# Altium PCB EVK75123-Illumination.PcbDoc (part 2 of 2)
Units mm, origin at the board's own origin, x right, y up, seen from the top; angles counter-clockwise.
Board outline 80 x 50 mm, 4 copper layers (Top Layer, GND, VCC, Bottom Layer), stack 0.976 mm thick; 91 components, 44 nets, 247 pads, 1773 vias.
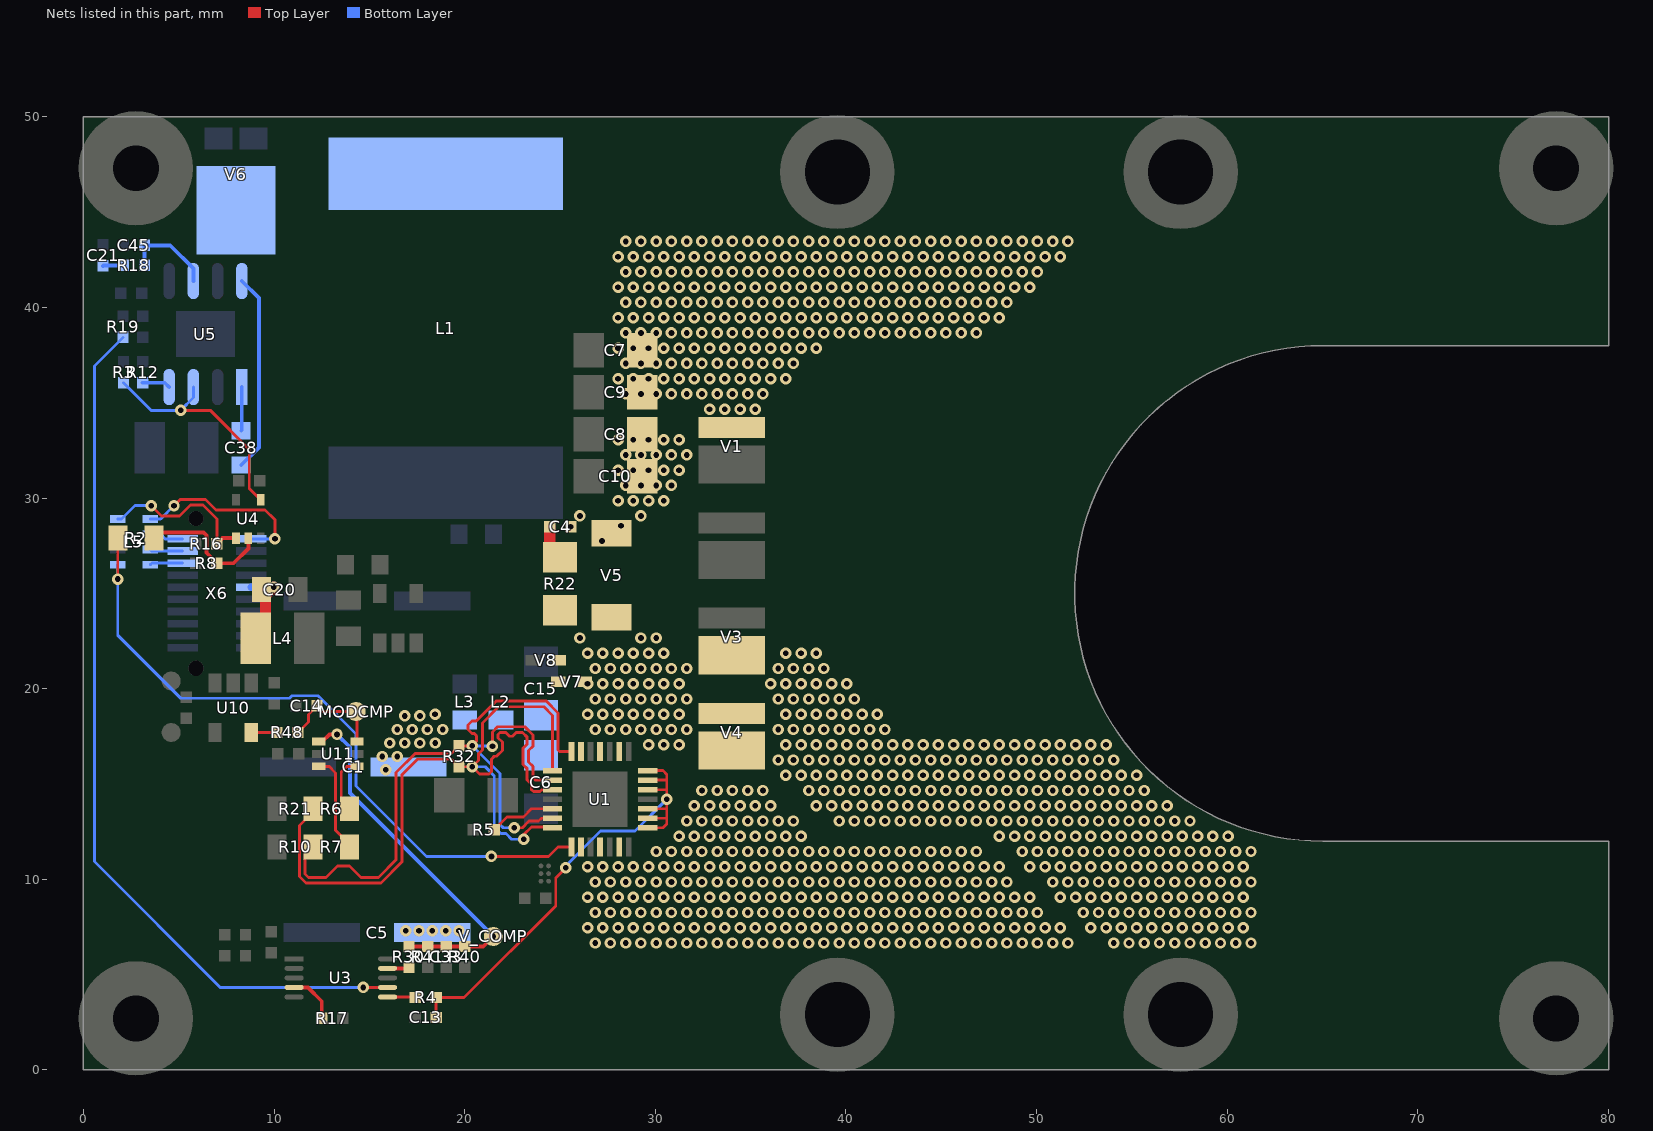
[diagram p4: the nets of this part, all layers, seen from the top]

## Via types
v1: diameter 0.6, hole 0.3, Top Layer to Bottom Layer, tented both sides, 1773 vias

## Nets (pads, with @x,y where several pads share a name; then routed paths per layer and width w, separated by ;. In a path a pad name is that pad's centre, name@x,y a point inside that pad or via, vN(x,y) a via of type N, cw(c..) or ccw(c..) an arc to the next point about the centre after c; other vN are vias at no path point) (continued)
LD3: V3.2 V4.1
  other v1: 54.044,6.659 54.844,6.659 55.644,6.659 56.444,6.659 57.244,6.659 58.044,6.659 58.844,6.659 59.644,6.659 60.444,6.659 61.244,6.659 52.844,7.459 53.644,7.459 54.444,7.459 55.244,7.459 56.044,7.459 56.844,7.459 57.644,7.459 58.444,7.459 59.244,7.459 60.044,7.459 60.844,7.459 52.444,8.259 53.244,8.259 54.044,8.259 54.844,8.259 55.644,8.259 56.444,8.259 57.244,8.259 58.044,8.259 58.844,8.259 59.644,8.259 60.444,8.259 61.244,8.259 51.244,9.059 52.044,9.059 52.844,9.059 53.644,9.059 54.444,9.059 55.244,9.059 56.044,9.059 56.844,9.059 57.644,9.059 58.444,9.059 59.244,9.059 60.044,9.059 60.844,9.059 50.844,9.859 51.644,9.859 52.444,9.859 53.244,9.859 54.044,9.859 54.844,9.859 55.644,9.859 56.444,9.859 57.244,9.859 58.044,9.859 58.844,9.859 59.644,9.859 60.444,9.859 61.244,9.859 49.644,10.659 50.444,10.659 51.244,10.659 52.044,10.659 52.844,10.659 53.644,10.659 54.444,10.659 55.244,10.659 56.044,10.659 56.844,10.659 57.644,10.659 58.444,10.659 59.244,10.659 60.044,10.659 60.844,10.659 49.244,11.459 50.044,11.459 50.844,11.459 51.644,11.459 52.444,11.459 53.244,11.459 54.044,11.459 54.844,11.459 55.644,11.459 56.444,11.459 57.244,11.459 58.044,11.459 58.844,11.459 59.644,11.459 60.444,11.459 61.244,11.459 48.044,12.259 48.844,12.259 49.644,12.259 50.444,12.259 51.244,12.259 52.044,12.259 52.844,12.259 53.644,12.259 54.444,12.259 55.244,12.259 56.044,12.259 56.844,12.259 57.644,12.259 58.444,12.259 59.244,12.259 60.044,12.259 39.644,13.059 40.444,13.059 41.244,13.059 42.044,13.059 42.844,13.059 43.644,13.059 44.444,13.059 45.244,13.059 46.044,13.059 46.844,13.059 47.644,13.059 48.444,13.059 49.244,13.059 50.044,13.059 50.844,13.059 51.644,13.059 52.444,13.059 53.244,13.059 54.044,13.059 54.844,13.059 55.644,13.059 56.444,13.059 57.244,13.059 58.044,13.059 38.444,13.859 39.244,13.859 40.044,13.859 40.844,13.859 41.644,13.859 42.444,13.859 43.244,13.859 44.044,13.859 44.844,13.859 45.644,13.859 46.444,13.859 47.244,13.859 48.044,13.859 48.844,13.859 49.644,13.859 50.444,13.859 51.244,13.859 52.044,13.859 52.844,13.859 53.644,13.859 54.444,13.859 55.244,13.859 56.044,13.859 56.844,13.859 38.044,14.659 38.844,14.659 39.644,14.659 40.444,14.659 41.244,14.659 42.044,14.659 42.844,14.659 43.644,14.659 44.444,14.659 45.244,14.659 46.044,14.659 46.844,14.659 47.644,14.659 48.444,14.659 49.244,14.659 50.044,14.659 50.844,14.659 51.644,14.659 52.444,14.659 53.244,14.659 54.044,14.659 54.844,14.659 55.644,14.659 36.844,15.459 37.644,15.459 38.444,15.459 39.244,15.459 40.044,15.459 40.844,15.459 41.644,15.459 42.444,15.459 43.244,15.459 44.044,15.459 44.844,15.459 45.644,15.459 46.444,15.459 47.244,15.459 48.044,15.459 48.844,15.459 49.644,15.459 50.444,15.459 51.244,15.459 52.044,15.459 52.844,15.459 53.644,15.459 54.444,15.459 55.244,15.459 36.444,16.259 37.244,16.259 38.044,16.259 38.844,16.259 39.644,16.259 40.444,16.259 41.244,16.259 42.044,16.259 42.844,16.259 43.644,16.259 44.444,16.259 45.244,16.259 46.044,16.259 46.844,16.259 47.644,16.259 48.444,16.259 49.244,16.259 50.044,16.259 50.844,16.259 51.644,16.259 52.444,16.259 53.244,16.259 54.044,16.259 36.844,17.059 37.644,17.059 38.444,17.059 39.244,17.059 40.044,17.059 40.844,17.059 41.644,17.059 42.444,17.059 43.244,17.059 44.044,17.059 44.844,17.059 45.644,17.059 46.444,17.059 47.244,17.059 48.044,17.059 48.844,17.059 49.644,17.059 50.444,17.059 51.244,17.059 52.044,17.059 52.844,17.059 53.644,17.059 36.444,17.859 37.244,17.859 38.044,17.859 38.844,17.859 39.644,17.859 40.444,17.859 41.244,17.859 42.044,17.859 36.844,18.659 37.644,18.659 38.444,18.659 39.244,18.659 40.044,18.659 40.844,18.659 41.644,18.659 36.444,19.459 37.244,19.459 38.044,19.459 38.844,19.459 39.644,19.459 40.444,19.459 36.044,20.259 36.844,20.259 37.644,20.259 38.444,20.259 39.244,20.259 40.044,20.259 36.444,21.059 37.244,21.059 38.044,21.059 38.844,21.059 36.844,21.859 37.644,21.859 38.444,21.859
LDEN: L5.4 R16.1 U4.1 | length 8.7
  Top Layer w0.15: v1(3.55,29.6) 4.096,29.054 5.032,29.054 5.608,29.63 6.27,29.63 7,28.9 R16.1@7,27.6
  Top Layer w0.2: R16.1@7,27.6 7.3,27.9 U4.1@8,27.9
  Bottom Layer w0.15: L5.4@1.8,28.9 2,28.9 2.7,29.6 v1(3.55,29.6)
LDK: R22.1 U1.9 U1.11 U1.13 U1.23 U1.25 U1.27 V4.2 V5.1 V7.2
  other v1: 26.844,6.659 27.644,6.659 28.444,6.659 29.244,6.659 30.044,6.659 30.844,6.659 31.644,6.659 32.444,6.659 33.244,6.659 34.044,6.659 34.844,6.659 35.644,6.659 36.444,6.659 37.244,6.659 38.044,6.659 38.844,6.659 39.644,6.659 40.444,6.659 41.244,6.659 42.044,6.659 42.844,6.659 43.644,6.659 44.444,6.659 45.244,6.659 46.044,6.659 46.844,6.659 47.644,6.659 48.444,6.659 49.244,6.659 50.044,6.659 50.844,6.659 51.644,6.659 26.444,7.459 27.244,7.459 28.044,7.459 28.844,7.459 29.644,7.459 30.444,7.459 31.244,7.459 32.044,7.459 32.844,7.459 33.644,7.459 34.444,7.459 35.244,7.459 36.044,7.459 36.844,7.459 37.644,7.459 38.444,7.459 39.244,7.459 40.044,7.459 40.844,7.459 41.644,7.459 42.444,7.459 43.244,7.459 44.044,7.459 44.844,7.459 45.644,7.459 46.444,7.459 47.244,7.459 48.044,7.459 48.844,7.459 49.644,7.459 50.444,7.459 51.244,7.459 26.844,8.259 27.644,8.259 28.444,8.259 29.244,8.259 30.044,8.259 30.844,8.259 31.644,8.259 32.444,8.259 33.244,8.259 34.044,8.259 34.844,8.259 35.644,8.259 36.444,8.259 37.244,8.259 38.044,8.259 38.844,8.259 39.644,8.259 40.444,8.259 41.244,8.259 42.044,8.259 42.844,8.259 43.644,8.259 44.444,8.259 45.244,8.259 46.044,8.259 46.844,8.259 47.644,8.259 48.444,8.259 49.244,8.259 50.044,8.259 26.444,9.059 27.244,9.059 28.044,9.059 28.844,9.059 29.644,9.059 30.444,9.059 31.244,9.059 32.044,9.059 32.844,9.059 33.644,9.059 34.444,9.059 35.244,9.059 36.044,9.059 36.844,9.059 37.644,9.059 38.444,9.059 39.244,9.059 40.044,9.059 40.844,9.059 41.644,9.059 42.444,9.059 43.244,9.059 44.044,9.059 44.844,9.059 45.644,9.059 46.444,9.059 47.244,9.059 48.044,9.059 48.844,9.059 49.644,9.059 26.844,9.859 27.644,9.859 28.444,9.859 29.244,9.859 30.044,9.859 30.844,9.859 31.644,9.859 32.444,9.859 33.244,9.859 34.044,9.859 34.844,9.859 35.644,9.859 36.444,9.859 37.244,9.859 38.044,9.859 38.844,9.859 39.644,9.859 40.444,9.859 41.244,9.859 42.044,9.859 42.844,9.859 43.644,9.859 44.444,9.859 45.244,9.859 46.044,9.859 46.844,9.859 47.644,9.859 48.444,9.859 26.444,10.659 27.244,10.659 28.044,10.659 28.844,10.659 29.644,10.659 30.444,10.659 31.244,10.659 32.044,10.659 32.844,10.659 33.644,10.659 34.444,10.659 35.244,10.659 36.044,10.659 36.844,10.659 37.644,10.659 38.444,10.659 39.244,10.659 40.044,10.659 40.844,10.659 41.644,10.659 42.444,10.659 43.244,10.659 44.044,10.659 44.844,10.659 45.644,10.659 46.444,10.659 47.244,10.659 48.044,10.659 30.044,11.459 30.844,11.459 31.644,11.459 32.444,11.459 33.244,11.459 34.044,11.459 34.844,11.459 35.644,11.459 36.444,11.459 37.244,11.459 38.044,11.459 38.844,11.459 39.644,11.459 40.444,11.459 41.244,11.459 42.044,11.459 42.844,11.459 43.644,11.459 44.444,11.459 45.244,11.459 46.044,11.459 46.844,11.459 31.244,12.259 32.044,12.259 32.844,12.259 33.644,12.259 34.444,12.259 35.244,12.259 36.044,12.259 36.844,12.259 37.644,12.259 31.644,13.059 32.444,13.059 33.244,13.059 34.044,13.059 34.844,13.059 35.644,13.059 36.444,13.059 37.244,13.059 32.044,13.859 32.844,13.859 33.644,13.859 34.444,13.859 35.244,13.859 36.044,13.859 32.444,14.659 33.244,14.659 34.044,14.659 34.844,14.659 35.644,14.659 29.644,17.059 30.444,17.059 31.244,17.059 26.844,17.859 27.644,17.859 28.444,17.859 29.244,17.859 30.044,17.859 30.844,17.859 31.644,17.859 26.444,18.659 27.244,18.659 28.044,18.659 28.844,18.659 29.644,18.659 30.444,18.659 31.244,18.659 26.844,19.459 27.644,19.459 28.444,19.459 29.244,19.459 30.044,19.459 30.844,19.459 31.644,19.459 26.444,20.259 27.244,20.259 28.044,20.259 28.844,20.259 29.644,20.259 30.444,20.259 31.244,20.259 26.844,21.059 27.644,21.059 28.444,21.059 29.244,21.059 30.044,21.059 30.844,21.059 31.644,21.059 26.444,21.859 27.244,21.859 28.044,21.859 28.844,21.859 29.644,21.859 30.444,21.859 26.044,22.659 29.244,22.659 30.044,22.659
MOD1_N: R7.2 U11.6 | length 5.2
  Top Layer w0.15: U11.6@12.35,15.925 12.875,15.925 13.225,15.575 13.225,12.575 13.95,11.85 R7.2@13.95,11.7
MOD1_P: R6.2 U11.1 | length 3.1
  Top Layer w0.15: R6.2@13.95,13.7 13.525,14.125 13.525,15.625 13.825,15.925 U11.1@14.35,15.925
MOD_CMP: C14.2 MODCMP.1 R48.2 U11.3 | length 5.6
  Top Layer w0.15: R48.2@11.25,17.7 11.8,18.25 11.8,18.65 C14.2@12.25,19.1 12.55,18.8 MODCMP.1@14.3,18.8 14.35,18.75 U11.3@14.35,17.225
MOD_N: R7.1 R10.1 R32.1 U1.14 U1.16 U1.20 | length 41.6
  Top Layer w0.15: R7.1@12.05,11.7 11.625,11.275 11.625,10.275 11.8,10.1 12.719,10.1 13.319,10.7 13.957,10.7 14.557,10.1 15.476,10.1 16.4,11.024 16.4,15.6 17.4,16.6 19.3,16.6 R32.1@19.7,17 v1(20.4,17) 20.625,17.225 20.625,17.525 20.5,17.65 20.375,17.65 20.175,17.85 20.175,18.1 20.375,18.3 20.6,18.3 21.65,19.35 24.274,19.35 24.9,18.724 24.9,16.775 24.975,16.7 U1.14@25.6,16.7 ; v1(21.452,16.977) 21.452,17.727 21.726,18 23.15,18 23.575,17.575 23.575,16.975 23.35,16.75 23.35,16.15 23.575,15.925 23.575,15.325 23.7,15.2 U1.16@24.6,15.2 ; v1(22.6,12.7) 23.026,12.7 23.376,13.05 23.875,13.05 24.025,13.2 U1.20@24.6,13.2
  Bottom Layer w0.15: v1(21.452,16.977) 21.429,17 v1(20.4,17) 21.85,15.55 21.85,12.874 22.024,12.7 v1(22.6,12.7)
MOD_P: R6.1 R21.1 R32.2 U1.15 U1.17 U1.21 | length 45.6
  Top Layer w0.15: R6.1@12.05,13.7 12.05,13.55 11.325,12.825 11.325,10.151 11.676,9.8 15.6,9.8 16.7,10.9 16.7,15.476 17.524,16.3 19.3,16.3 R32.2@19.7,15.9 v1(20.4,15.9) ; v1(23.1,12.1) 23.1,12.35 23.5,12.75 24.55,12.75 U1.21@24.6,12.7 ; U1.17@24.6,14.7 24.175,14.7 24.05,14.7 23.95,14.6 23.6,14.6 23.5,14.7 23.5,14.976 23.275,15.201 23.275,15.801 23.05,16.026 23.05,16.874 23.275,17.099 23.275,17.451 23.026,17.7 22.7,17.7 22.5,17.5 22.35,17.5 22.15,17.7 21.85,17.7 21.752,17.602 21.752,17.419 21.977,17.194 21.977,16.759 21.67,16.452 21.552,16.452 21.4,16.3 21.4,15.65 21.275,15.525 20.775,15.525 v1(20.4,15.9) ; U1.15@24.6,15.7 24.6,18.6 24.15,19.05 21.774,19.05 20.925,18.201 20.925,16.783 20.725,16.583 20.725,16.225 v1(20.4,15.9)
  Bottom Layer w0.15: v1(20.4,15.9) 21.076,15.9 21.55,15.426 21.55,12.75 21.9,12.4 22.157,12.4 22.457,12.1 v1(23.1,12.1)
MOD_SE: R48.1 U10.5 | length 1.3
  Top Layer w0.15: U10.5@8.8,17.7 R48.1@10.15,17.7
NERR: L5.1 R2.1 U1.22 | length 36.4
  Top Layer w0.15: v1(1.8,25.75) R2.1@1.8,27.9 ; v1(21.4,11.2) 24.4,11.2 24.9,11.7 U1.22@25.6,11.7
  Bottom Layer w0.15: L5.1@1.8,26.5 v1(1.8,25.75) 1.8,22.8 5.1,19.5 10.808,19.5 10.933,19.625 12.304,19.625 14.3,17.629 14.3,14.9 18,11.2 v1(21.4,11.2)
NERRR: R2.2 R8.1 U4.2 | length 7.2
  Top Layer w0.2: R2.2@3.7,27.9 3.995,28.195 6.305,28.195 6.45,28.05 6.45,27.125 R8.1@7,26.575 7.875,26.575 8.65,27.35 U4.2@8.65,27.9
NetC4_1: C4.1 R22.2 | length 1.1
  Top Layer w0.6: R22.2@24.45,27.45 C4.1@24.45,28.5
NetC13_2: C13.2 R4.1 U1.1 U1.2 U1.3 U1.5 U1.6 U1.7 | length 27.1
  Top Layer w0.15: C13.2@18.5,2.75 R4.1@18.5,3.8 19.968,3.8 24.775,8.607 24.775,10.075 v1(25.3,10.6) ; U1.1@29.6,12.7 30.4,12.7 30.6,12.9 30.6,13.2 ; U1.2@29.6,13.2 30.6,13.2 ; U1.3@29.6,13.7 30.6,13.7 ; U1.5@29.6,14.7 30.6,14.7 ; U1.6@29.6,15.2 30.6,15.2 ; U1.7@29.6,15.7 30.4,15.7 30.6,15.5 30.6,15.2 ; 30.6,13.2 30.6,13.7 ; 30.6,13.7 v1(30.6,14.2) 30.6,14.7 ; 30.6,14.7 30.6,15.2
  Bottom Layer w0.15: v1(25.3,10.6) 25.3,10.7 27.125,12.525 28.925,12.525 v1(30.6,14.2)
NetC20_2: C20.2 L4.1 X6.11 | length 4.2
  Top Layer w0.6: L4.1@9.05,22.65 9.05,23.25 9.55,23.75 9.55,24.885 v1(9.982,25.318)
  Bottom Layer w0.4: X6.11@8.8,25.318 v1(9.982,25.318)
NetC21_2: C21.2 R18.2 | length 1.1
  Bottom Layer w0.2: C21.2@1.025,42.175 1.05,42.2 R18.2@2.1,42.2
NetC38_2: C38.2 U5.1 | length 2.3
  Bottom Layer w0.2: C38.2@8.275,33.525 8.305,33.555 U5.1@8.305,35.82
NetC45_2: C45.2 R18.1 U5.6 | length 4.8
  Bottom Layer w0.2: R18.1@3.2,42.2 C45.2@3.2,43.25 4.55,43.25 5.765,42.035 U5.6@5.765,41.38
NetL5_5: L5.5 X6.19 | length 9.7
  Top Layer w0.15: v1(4.75,29.6) 5.08,29.93 6.394,29.93 6.949,29.375 9.525,29.375 10.042,28.858 v1(10.042,27.858)
  Bottom Layer w0.15: L5.5@3.5,28.9 4.05,28.9 v1(4.75,29.6) ; X6.19@8.8,27.858 v1(10.042,27.858)
NetL5_6: L5.6 X6.20 | length 1.8
  Bottom Layer w0.15: L5.6@3.5,28.1 4.05,28.1 4.292,27.858 X6.20@5.2,27.858
NetL5_7: L5.7 X6.18 | length 1.7
  Bottom Layer w0.15: L5.7@3.5,27.3 3.578,27.223 X6.18@5.2,27.223
NetL5_8: L5.8 X6.16 | length 1.7
  Bottom Layer w0.15: L5.8@3.5,26.5 3.588,26.588 X6.16@5.2,26.588
NetR5_1: R5.1 U1.19 | length 3.5
  Top Layer w0.15: R5.1@21.55,12.6 22.225,13.275 23.075,13.275 23.5,13.7 U1.19@24.6,13.7
NetR17_2: R17.2 U3.4 | length 2.7
  Top Layer w0.2: U3.4@11.05,4.325 11.775,4.325 12.5,3.6 R17.2@12.5,2.7
NetV7_1: V7.1 V8.2
PEN: R3.2 U4.4 U5.3 | length 12.4
  Top Layer w0.15: v1(5.1,34.6) 6.65,34.6 8.7,32.55 8.7,30.5 U4.4@9.3,29.9
  Bottom Layer w0.15: R3.2@2.1,36.05 3.55,34.6 v1(5.1,34.6) 5.765,35.265 U5.3@5.765,35.82
RT17V: R12.1 U5.4 | length 1.5
  Bottom Layer w0.2: R12.1@3.1,36.05 4.265,36.05 U5.4@4.495,35.82
SW17V: C38.1 L1.1 U5.8 V6.2 | length 10.4
  Bottom Layer w0.2: C38.1@8.275,31.725 9.2,32.65 9.2,40.485 U5.8@8.305,41.38
V_CI: R4.2 U3.6 | length 1.5
  Top Layer w0.15: U3.6@15.95,3.825 17.375,3.825 R4.2@17.4,3.8
V_CMP: C33.1 R30.2 R40.2 R41.1 U11.4 V_COMP.1 | length 19.7
  Top Layer w0.2: U11.4@12.35,17.225 12.525,17.225 12.9,17.6 v1(13.3,17.6) ; R30.2@17.075,6.475 20.975,6.475 v1(21.5,7)
  Bottom Layer w0.2: v1(13.3,17.6) 13.975,16.925 13.975,14.525 v1(21.5,7)
V_DAC_D: R30.1 U3.9 | length 1.1
  Top Layer w0.2: U3.9@15.95,5.325 17.025,5.325 R30.1@17.075,5.375
VLD: C1.1 C4.2 C5.1 C6.1 C7.2 C8.2 C9.2 C10.2 C15.2 L2.2 L3.2 V1.1 V5.2
  other v1: 16.9,7.3 17.6,7.3 18.3,7.3 19,7.3 19.7,7.3 15.856,15.741 15.669,16.441 16.456,16.441 16.063,17.15 16.85,17.15 17.65,17.15 18.45,17.15 16.456,17.859 17.244,17.859 18.044,17.859 18.844,17.859 16.85,18.567 17.65,18.567 18.444,18.659 27.2,27.75 25.55,28.5 28.2,28.55 26.044,29.059 29.244,29.059 28.044,29.859 28.844,29.859 29.644,29.859 30.444,29.859 28.444,30.659 29.244,30.659 30.044,30.659 30.844,30.659 28.044,31.459 28.844,31.459 29.644,31.459 30.444,31.459 31.244,31.459 28.444,32.259 29.244,32.259 30.044,32.259 30.844,32.259 31.644,32.259 28.044,33.059 28.844,33.059 29.644,33.059 30.444,33.059 31.244,33.059 32.844,34.659 33.644,34.659 34.444,34.659 35.244,34.659 28.444,35.459 29.244,35.459 30.044,35.459 30.844,35.459 31.644,35.459 32.444,35.459 33.244,35.459 34.044,35.459 34.844,35.459 35.644,35.459 28.044,36.259 28.844,36.259 29.644,36.259 30.444,36.259 31.244,36.259 32.044,36.259 32.844,36.259 33.644,36.259 34.444,36.259 35.244,36.259 36.044,36.259 36.844,36.259 28.444,37.059 29.244,37.059 30.044,37.059 30.844,37.059 31.644,37.059 32.444,37.059 33.244,37.059 34.044,37.059 34.844,37.059 35.644,37.059 36.444,37.059 37.244,37.059 28.044,37.859 28.844,37.859 29.644,37.859 30.444,37.859 31.244,37.859 32.044,37.859 32.844,37.859 33.644,37.859 34.444,37.859 35.244,37.859 36.044,37.859 36.844,37.859 37.644,37.859 38.444,37.859 28.444,38.659 29.244,38.659 30.044,38.659 30.844,38.659 31.644,38.659 32.444,38.659 33.244,38.659 34.044,38.659 34.844,38.659 35.644,38.659 36.444,38.659 37.244,38.659 38.044,38.659 38.844,38.659 39.644,38.659 40.444,38.659 41.244,38.659 42.044,38.659 42.844,38.659 43.644,38.659 44.444,38.659 45.244,38.659 46.044,38.659 46.844,38.659 28.044,39.459 28.844,39.459 29.644,39.459 30.444,39.459 31.244,39.459 32.044,39.459 32.844,39.459 33.644,39.459 34.444,39.459 35.244,39.459 36.044,39.459 36.844,39.459 37.644,39.459 38.444,39.459 39.244,39.459 40.044,39.459 40.844,39.459 41.644,39.459 42.444,39.459 43.244,39.459 44.044,39.459 44.844,39.459 45.644,39.459 46.444,39.459 47.244,39.459 48.044,39.459 28.444,40.259 29.244,40.259 30.044,40.259 30.844,40.259 31.644,40.259 32.444,40.259 33.244,40.259 34.044,40.259 34.844,40.259 35.644,40.259 36.444,40.259 37.244,40.259 38.044,40.259 38.844,40.259 39.644,40.259 40.444,40.259 41.244,40.259 42.044,40.259 42.844,40.259 43.644,40.259 44.444,40.259 45.244,40.259 46.044,40.259 46.844,40.259 47.644,40.259 48.444,40.259 28.044,41.059 28.844,41.059 29.644,41.059 30.444,41.059 31.244,41.059 32.044,41.059 32.844,41.059 33.644,41.059 34.444,41.059 35.244,41.059 36.044,41.059 36.844,41.059 37.644,41.059 38.444,41.059 39.244,41.059 40.044,41.059 40.844,41.059 41.644,41.059 42.444,41.059 43.244,41.059 44.044,41.059 44.844,41.059 45.644,41.059 46.444,41.059 47.244,41.059 48.044,41.059 48.844,41.059 49.644,41.059 28.444,41.859 29.244,41.859 30.044,41.859 30.844,41.859 31.644,41.859 32.444,41.859 33.244,41.859 34.044,41.859 34.844,41.859 35.644,41.859 36.444,41.859 37.244,41.859 38.044,41.859 38.844,41.859 39.644,41.859 40.444,41.859 41.244,41.859 42.044,41.859 42.844,41.859 43.644,41.859 44.444,41.859 45.244,41.859 46.044,41.859 46.844,41.859 47.644,41.859 48.444,41.859 49.244,41.859 50.044,41.859 28.044,42.659 28.844,42.659 29.644,42.659 30.444,42.659 31.244,42.659 32.044,42.659 32.844,42.659 33.644,42.659 34.444,42.659 35.244,42.659 36.044,42.659 36.844,42.659 37.644,42.659 38.444,42.659 39.244,42.659 40.044,42.659 40.844,42.659 41.644,42.659 42.444,42.659 43.244,42.659 44.044,42.659 44.844,42.659 45.644,42.659 46.444,42.659 47.244,42.659 48.044,42.659 48.844,42.659 49.644,42.659 50.444,42.659 51.244,42.659 28.444,43.459 29.244,43.459 30.044,43.459 30.844,43.459 31.644,43.459 32.444,43.459 33.244,43.459 34.044,43.459 34.844,43.459 35.644,43.459 36.444,43.459 37.244,43.459 38.044,43.459 38.844,43.459 39.644,43.459 40.444,43.459 41.244,43.459 42.044,43.459 42.844,43.459 43.644,43.459 44.444,43.459 45.244,43.459 46.044,43.459 46.844,43.459 47.644,43.459 48.444,43.459 49.244,43.459 50.044,43.459 50.844,43.459 51.644,43.459
VPROG: R19.2 U3.7 | length 46.2
  Top Layer w0.15: v1(14.675,4.325) U3.7@15.95,4.325
  Bottom Layer w0.15: R19.2@2.075,38.425 0.575,36.925 0.575,10.925 7.175,4.325 v1(14.675,4.325)
pads on no net: P1.1 P2.1 P3.1 P4.1 P5.1 P6.1 PCB.1 U2.C1 U3.5 U3.8 U6.4 X6.12 X6.A1 X6.A2

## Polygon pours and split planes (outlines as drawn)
LDK on Top Layer "LDK" (solid, remove dead copper, pour order 0): 25.9,15.1 25.9,13.2 25.9,6 53.5,6 47.3,12.2 38.9,12.2 35.75,15.35 35.75,17.75 32,17.75 32,21.5 28.8,24.7 24.1,24.7 24.1,23.1 25.9,21.3 25.9,20.7
VLD on Top Layer "VLD" (solid, remove dead copper, pour order 2): 25.2,28 25.2,29.5 25.7,30 27.5,31.8 27.5,32.2 27.5,44 53.4,44 47.1,37.7 39.1,37.7 35.75,34.35 35.75,33.15 32.05,33.15 32,33.1 32,30.6 28.8,27.4 25.2,27.4
LD2 on Top Layer "LD2" (solid, remove dead copper, pour order 8): 28.8,34.05 61.2,34.05 61.2,15.8 28.8,15.8
LD1 on Top Layer "LD1" (solid, remove dead copper, pour order 4): 32.25,28 32.25,39.51 35.75,43.01 36.84,44.1 62,44.1 62,32.4 43.2,32.4 38.8,28
LD3 on Top Layer "LD3" (solid, remove dead copper, pour order 6): 32.25,22.8 32.25,9.5 35.75,6 62,6 62,17.8 43.2,17.8 38.2,22.8
GND on Top Layer "GND" (solid, remove dead copper, pour order 24): 0,0 0,50 80,50 80,0
LD3 on Bottom Layer "LD3" (solid, remove dead copper, pour order 14): 32.25,22.8 32.25,9.5 35.75,6 62,6 62,17.8 43.2,17.8 38.2,22.8
LD1 on Bottom Layer "LD1" (solid, remove dead copper, pour order 16): 32.25,28 32.25,33.45 42.9,44.1 62,44.1 62,32.4 43.2,32.4 38.8,28
LD2 on Bottom Layer "LD2" (solid, remove dead copper, pour order 18): 28.8,34.05 61.2,34.05 61.2,15.9 28.8,15.9
VLD on Bottom Layer "VLD" (solid, remove dead copper, pour order 12): 25.2,28 25.2,29.5 25.7,30 27.5,31.8 27.5,32.2 27.5,44 53.4,44 47.1,37.7 39.1,37.7 35.75,34.35 35.75,33.15 32.05,33.15 32,33.1 32,30.6 28.8,27.4 25.2,27.4
LDK on Bottom Layer "LDK" (solid, remove dead copper, pour order 10): 28.8,15.85 28.8,12.5 25.9,12.5 25.9,6 53.5,6 47.3,12.2 39.3,12.2 35.75,15.75 35.75,17.75 32,17.75 32,21.5 28.8,24.7 24.1,24.7 24.1,23.1 25.9,21.3 25.9,15.85
VLD on Bottom Layer "VLD" (solid, remove dead copper, pour order 20): 24.9,19.4 17.25,19.4 15.05,17.2 15.05,15.4 18.8,15.4 20.4,17 21.429,17 21.452,16.977 22.729,15.7 23.95,15.7 24.9,15.7
GND on Bottom Layer "GND" (solid, remove dead copper, pour order 22): 0,0 0,50 80,50 80,0
LD1 on GND (split plane): 61.948,43.996 61.948,37.843 61.583,37.752 61.109,37.616 60.64,37.461 60.177,37.29 59.721,37.101 59.272,36.895 58.831,36.672 58.399,36.434 57.976,36.179 57.563,35.908 57.16,35.623 56.768,35.322 56.388,35.007 56.02,34.678 55.665,34.335 55.322,33.98 54.993,33.612 54.678,33.232 54.377,32.84 54.173,32.552 43.3,32.552 43.235,32.544 43.174,32.518 43.122,32.478 38.996,28.352 36.152,28.352 36.152,34.396 39.204,37.448 47.1,37.448 47.165,37.456 47.226,37.482 47.278,37.522 53.478,43.722 53.501,43.751 53.518,43.774 53.526,43.792 53.544,43.835 53.552,43.9 53.552,44.148 61.796,44.148
LD2 on GND (split plane): 53.821,32.024 53.566,31.601 53.328,31.169 53.105,30.728 52.899,30.279 52.71,29.823 52.539,29.36 52.384,28.891 52.248,28.417 52.129,27.938 52.028,27.454 51.945,26.968 51.881,26.478 51.835,25.987 51.807,25.494 51.798,25 51.807,24.506 51.835,24.013 51.881,23.522 51.945,23.032 52.028,22.546 52.129,22.062 52.248,21.583 52.384,21.109 52.539,20.64 52.71,20.177 52.899,19.721 53.105,19.272 53.328,18.831 53.566,18.399 53.715,18.152 43.304,18.152 38.578,22.878 38.526,22.918 38.465,22.944 38.4,22.952 36.152,22.952 36.152,27.848 39.1,27.848 39.165,27.856 39.226,27.882 39.278,27.922 43.404,32.048 53.837,32.048
LD3 on GND (split plane): 43.022,17.722 43.074,17.682 43.135,17.656 43.2,17.648 54.036,17.648 54.092,17.563 54.377,17.16 54.678,16.768 54.993,16.388 55.322,16.02 55.665,15.665 56.02,15.322 56.388,14.993 56.768,14.678 57.16,14.377 57.563,14.092 57.976,13.821 58.399,13.566 58.831,13.328 59.272,13.105 59.721,12.899 60.177,12.71 60.64,12.539 61.109,12.384 61.583,12.248 61.948,12.157 61.948,6.104 61.896,6.052 53.552,6.052 53.552,6.3 53.544,6.365 53.518,6.426 53.496,6.456 53.478,6.478 47.478,12.478 47.426,12.518 47.365,12.544 47.3,12.552 39.104,12.552 35.957,15.7 36.078,15.822 36.096,15.844 36.118,15.874 36.144,15.935 36.152,16 36.152,22.448 38.296,22.448
LDK on GND (split plane): 38.822,12.122 38.874,12.082 38.935,12.056 39,12.048 47.196,12.048 53.048,6.196 53.048,6.052 26.804,6.052 25.552,7.304 25.552,9.596 26.504,10.548 29.3,10.548 29.365,10.556 29.426,10.582 29.478,10.622 32.078,13.222 32.118,13.274 32.144,13.335 32.152,13.4 32.152,14.496 32.504,14.848 35,14.848 35.065,14.856 35.126,14.882 35.178,14.922 35.6,15.343
VLD on GND (split plane): 53.048,44.004 46.996,37.952 39.1,37.952 39.035,37.944 38.974,37.918 38.922,37.878 35.9,34.857 31.478,39.278 31.426,39.318 31.365,39.344 31.3,39.352 27.604,39.352 27.452,39.504 27.452,43.296 28.304,44.148 53.048,44.148
GND on GND (split plane): 79.798,38.202 65,38.202 64.506,38.193 64.013,38.165 63.522,38.119 63.032,38.055 62.546,37.972 62.452,37.953 62.452,44.1 62.444,44.165 62.418,44.226 62.378,44.278 62.078,44.578 62.026,44.618 61.965,44.644 61.9,44.652 28.2,44.652 28.135,44.644 28.074,44.618 28.044,44.596 28.022,44.578 27.022,43.578 26.982,43.526 26.956,43.465 26.948,43.4 26.948,39.4 26.956,39.335 26.982,39.274 27.022,39.222 27.322,38.922 27.374,38.882 27.435,38.856 27.5,38.848 31.196,38.848 35.648,34.396 35.648,16.104 34.896,15.352 32.4,15.352 32.335,15.344 32.274,15.318 32.222,15.278 31.722,14.778 31.682,14.726 31.656,14.665 31.648,14.6 31.648,13.504 29.196,11.052 26.4,11.052 26.335,11.044 26.274,11.018 26.222,10.978 25.122,9.878 25.082,9.826 25.056,9.765 25.048,9.7 25.048,7.2 25.056,7.135 25.082,7.074 25.122,7.022 26.522,5.622 26.574,5.582 26.635,5.556 26.7,5.548 62,5.548 62.065,5.556 62.126,5.582 62.178,5.622 62.378,5.822 62.418,5.874 62.444,5.935 62.452,6 62.452,12.047 62.546,12.028 63.032,11.945 63.522,11.881 64.013,11.835 64.506,11.807 65,11.798 79.798,11.798 79.798,0.202 0.202,0.202 0.202,49.798 79.798,49.798
LD1 on VCC (split plane): 61.948,43.996 61.948,37.946 61.557,37.849 61.079,37.711 60.607,37.556 60.14,37.383 59.681,37.192 59.228,36.985 58.784,36.761 58.349,36.52 57.923,36.263 57.507,35.991 57.101,35.703 56.706,35.4 56.323,35.083 55.952,34.751 55.594,34.406 55.249,34.048 54.917,33.677 54.6,33.294 54.297,32.899 54.009,32.493 53.981,32.451 43.3,32.451 43.261,32.446 43.224,32.431 43.193,32.407 38.837,28.051 32.413,28.051 32.301,28.163 32.301,30.45 32.301,32.687 32.363,32.749 35.7,32.749 35.739,32.754 35.776,32.769 35.807,32.793 36.007,32.993 36.031,33.024 36.046,33.061 36.051,33.1 36.051,34.337 39.163,37.449 47.1,37.449 47.139,37.454 47.176,37.469 47.207,37.493 53.707,43.993 53.731,44.024 53.746,44.061 53.751,44.1 53.751,44.148 61.796,44.148
LD2 on VCC (split plane): 53.737,32.077 53.48,31.651 53.239,31.216 53.015,30.772 52.808,30.319 52.617,29.86 52.444,29.393 52.289,28.921 52.151,28.443 52.031,27.96 51.93,27.473 51.846,26.983 51.781,26.489 51.735,25.994 51.707,25.497 51.698,25 51.707,24.503 51.735,24.006 51.781,23.511 51.846,23.017 51.93,22.527 52.031,22.04 52.151,21.557 52.289,21.079 52.444,20.607 52.617,20.14 52.808,19.681 53.015,19.228 53.239,18.784 53.48,18.349 53.659,18.051 43.263,18.051 38.257,23.057 38.226,23.081 38.211,23.087 38.189,23.096 38.15,23.101 32.3,23.101 32.261,23.096 32.224,23.081 32.193,23.057 32.043,22.907 32.019,22.876 32.004,22.839 31.999,22.8 31.999,22.051 31.813,22.051 27.789,26.075 31.999,30.285 31.999,28.1 32.004,28.061 32.019,28.024 32.043,27.993 32.243,27.793 32.274,27.769 32.311,27.754 32.35,27.749 38.9,27.749 38.939,27.754 38.961,27.763 38.976,27.769 39.007,27.793 43.363,32.149 53.783,32.149
LD3 on VCC (split plane): 43.093,17.793 43.124,17.769 43.161,17.754 43.2,17.749 53.851,17.749 54.009,17.507 54.297,17.101 54.6,16.706 54.917,16.323 55.249,15.952 55.594,15.594 55.952,15.249 56.323,14.917 56.706,14.6 57.101,14.297 57.507,14.009 57.923,13.737 58.349,13.48 58.784,13.239 59.228,13.015 59.681,12.808 60.14,12.617 60.607,12.444 61.079,12.289 61.557,12.151 61.948,12.054 61.948,6.104 61.896,6.052 53.551,6.052 53.551,6.2 53.546,6.239 53.531,6.276 53.507,6.307 47.407,12.407 47.376,12.431 47.361,12.437 47.339,12.446 47.3,12.451 39.063,12.451 35.951,15.563 35.951,17.75 35.946,17.789 35.935,17.815 35.931,17.826 35.907,17.857 35.757,18.007 35.726,18.031 35.711,18.037 35.689,18.046 35.65,18.051 32.413,18.051 32.301,18.163 32.301,22.737 32.363,22.799 38.087,22.799
LDK on VCC (split plane): 31.643,21.793 31.674,21.769 31.711,21.754 31.75,21.749 31.999,21.749 31.999,21.65 31.999,18.1 32.004,18.061 32.019,18.024 32.043,17.993 32.243,17.793 32.274,17.769 32.311,17.754 32.35,17.749 35.587,17.749 35.649,17.687 35.649,15.5 35.654,15.461 35.669,15.424 35.693,15.393 38.893,12.193 38.924,12.169 38.961,12.154 39,12.149 47.237,12.149 53.249,6.137 53.249,6.052 26.604,6.052 25.502,7.154 25.502,9.2 25.494,9.265 25.468,9.326 25.428,9.378 24.778,10.028 24.726,10.068 24.665,10.094 24.6,10.102 23.802,10.102 23.802,15 23.794,15.065 23.768,15.126 23.728,15.178 22.878,16.028 22.851,16.049 22.851,21.137 27.575,25.861
VLD on VCC (split plane): 47.037,37.751 39.1,37.751 39.061,37.746 39.039,37.737 39.024,37.731 38.993,37.707 35.793,34.507 35.769,34.476 35.754,34.439 35.749,34.4 35.749,33.163 35.637,33.051 32.3,33.051 32.261,33.046 32.224,33.031 32.193,33.007 32.043,32.857 32.019,32.826 32.004,32.789 31.999,32.75 31.999,30.601 31.95,30.601 31.911,30.596 31.874,30.581 31.843,30.557 27.468,26.182 22.593,21.307 22.569,21.276 22.554,21.239 22.549,21.2 22.549,16.049 22.522,16.028 22.482,15.976 22.472,15.952 21.8,15.952 21.735,15.944 21.674,15.918 21.622,15.878 20.222,14.478 20.182,14.426 20.156,14.365 20.148,14.3 20.148,7.104 19.896,6.852 16.404,6.852 15.302,7.954 15.302,19.098 16.678,20.474 16.696,20.497 16.718,20.526 16.744,20.587 16.752,20.652 16.752,32.546 28.354,44.148 53.434,44.148
24V on VCC (split plane): 7.248,33.839 7.248,30.4 7.256,30.335 7.282,30.274 7.322,30.222 9.048,28.496 9.048,21.604 8.096,20.652 6.679,20.652 6.152,21.179 6.152,24.096 7.378,25.322 7.418,25.374 7.444,25.435 7.452,25.5 7.452,26.1 7.444,26.165 7.418,26.226 7.378,26.278 4.252,29.404 4.252,33.196 5.404,34.348 6.739,34.348
3V3 on VCC (split plane): 79.699,38.301 65,38.301 65,38.302 64.503,38.293 64.006,38.265 63.511,38.219 63.017,38.154 62.527,38.07 62.452,38.055 62.452,44.1 62.444,44.165 62.418,44.226 62.378,44.278 62.078,44.578 62.026,44.618 61.965,44.644 61.9,44.652 28.25,44.652 28.185,44.644 28.124,44.618 28.072,44.578 16.322,32.828 16.282,32.776 16.256,32.715 16.248,32.65 16.248,23.952 12.85,23.952 12.785,23.944 12.724,23.918 12.672,23.878 11.622,22.828 11.582,22.776 11.556,22.715 11.548,22.65 11.548,21.5 11.556,21.435 11.582,21.374 11.622,21.322 11.898,21.046 11.898,13.654 9.022,10.778 8.982,10.726 8.956,10.665 8.948,10.6 8.948,5.8 8.956,5.735 8.982,5.674 9.022,5.622 11.222,3.422 11.274,3.382 11.335,3.356 11.4,3.348 21.35,3.348 21.415,3.356 21.476,3.382 21.528,3.422 23.728,5.622 23.768,5.674 23.794,5.735 23.802,5.8 23.802,9.598 24.496,9.598 24.998,9.096 24.998,7.05 25.006,6.985 25.032,6.924 25.072,6.872 26.322,5.622 26.344,5.604 26.374,5.582 26.435,5.556 26.5,5.548 62,5.548 62.065,5.556 62.126,5.582 62.178,5.622 62.378,5.822 62.418,5.874 62.444,5.935 62.452,6 62.452,11.945 62.527,11.93 63.017,11.846 63.511,11.781 64.006,11.735 64.503,11.707 65,11.698 65,11.699 79.699,11.699 79.699,0.301 0.301,0.301 0.301,49.699 79.699,49.699
5V0 on VCC (split plane): 16.248,20.757 14.872,19.38 14.832,19.328 14.806,19.267 14.798,19.202 14.798,7.85 14.806,7.785 14.832,7.724 14.872,7.672 16.122,6.422 16.144,6.404 16.174,6.382 16.235,6.356 16.3,6.348 20,6.348 20.065,6.356 20.126,6.382 20.178,6.422 20.578,6.822 20.596,6.844 20.618,6.874 20.644,6.935 20.652,7 20.652,14.196 21.904,15.448 22.7,15.448 22.74,15.453 23.298,14.896 23.298,5.904 21.246,3.852 11.504,3.852 9.452,5.904 9.452,10.496 12.328,13.372 12.368,13.424 12.394,13.485 12.402,13.55 12.402,21.15 12.394,21.215 12.368,21.276 12.328,21.328 12.052,21.604 12.052,22.546 12.954,23.448 16.248,23.448

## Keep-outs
Keep-Out Layer:
  the board outline again, w0.2

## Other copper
Top Layer:
  region net NetV7_1: 25.3,21.75 24.55,21.75 24.55,20.1 25.3,20.1
  pour cut-out: 24.6,16.7 29.6,16.7 29.6,11.7 24.6,11.7
Bottom Layer:
  region net 17V: 20.4,29.4 20.4,25.9 22.6,23.7 22.6,19.7 18.1,19.7 16.3,21.5 16.3,29.4
  region net SW17V: 7.8,40.4 7.8,45.4 11.3,48.9 15.5,48.9 15.5,45.4 10.5,40.4
  region net 24V: 9.6,24.9 7.45,24.9 7.15,24.6 7.15,22.25 7.45,21.95 9.6,21.95
  region net GND: 6,24.9 3.85,24.9 3.55,24.6 3.55,22.25 3.85,21.95 6,21.95
GND (plane layer: these items are gaps in the copper):
  lines w0.5: 35.6,15.7 39,12.3 47.3,12.3 53.3,6.3 53.3,5.9 ; 35.9,22.7 38.4,22.7 43.2,17.9 62.2,17.9 ; 35.9,28.1 39.1,28.1 43.3,32.3 62.2,32.3 ; 53.3,44.4 53.3,43.9 47.1,37.7 39.1,37.7 35.9,34.5 ; 35.9,34.5 35.9,16 35,15.1 32.4,15.1 31.9,14.6 31.9,13.4 29.3,10.8 26.4,10.8 25.3,9.7 25.3,7.2 26.7,5.8 62,5.8 62.2,6 62.2,44.1 61.9,44.4 28.2,44.4 27.2,43.4 27.2,39.4 27.5,39.1 31.3,39.1 35.9,34.5
VCC (plane layer: these items are gaps in the copper):
  lines w0.3: 22.7,15.85 22.7,21.2 31.95,30.45 32.15,30.45 ; 27.575,26.075 31.75,21.9 32.15,21.9 32.15,21.65 ; 38.6,5.8 53.4,5.8 53.4,6.2 47.3,12.3 39,12.3 35.8,15.5 35.8,17.75 35.65,17.9 32.35,17.9 32.15,18.1 32.15,22.8 32.3,22.95 38.15,22.95 43.2,17.9 80,17.9 ; 53.6,44.3 53.6,44.1 47.1,37.6 39.1,37.6 35.9,34.4 35.9,33.1 35.7,32.9 32.3,32.9 32.15,32.75 32.15,30.45 ; 80,32.3 43.3,32.3 38.9,27.9 32.35,27.9 32.15,28.1 32.15,30.45
  lines w0.5: 16.5,23.7 12.85,23.7 11.8,22.65 11.8,21.5 12.15,21.15 12.15,13.55 9.2,10.6 9.2,5.8 11.4,3.6 21.35,3.6 23.55,5.8 23.55,15 22.7,15.85 ; 22.7,15.7 21.8,15.7 20.4,14.3 20.4,7 20,6.6 16.3,6.6 15.05,7.85 15.05,19.202 16.5,20.652 16.5,32.65 28.25,44.4 38.7,44.4 61.9,44.4 62.2,44.1 62.2,6 62,5.8 26.5,5.8 25.25,7.05 25.25,9.2 24.6,9.85 23.55,9.85 ; 4,29.3 4,33.3 5.3,34.6 6.843,34.6 7.5,33.943 7.5,30.4 9.3,28.6 9.3,21.5 8.2,20.4 6.575,20.4 5.9,21.075 5.9,24.2 7.2,25.5 7.2,26.1 4,29.3

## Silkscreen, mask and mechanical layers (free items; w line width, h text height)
Bottom Overlay:
  lines w0.2: 6,25 8,25 ; 7,24 7,26
Top Solder:
  drawing of 992 lines, arcs and shapes, not listed
  text "E" at 16.3,28.7 h5
  text ".prj_vers" at 24,3.45 h0.9
  text "G" at 71.8,1.1 h5
Bottom Solder:
  rectangle: 27.6,0 80,50.1
Boardoutline:
  the board outline again, w0.3
TopDimHUM:
  circle w0.1: c2.75,47.3 r1.2
BotDimHUM:
  circle w0.01: c39.55,47.1 r1.2
  circle w0.01: c39.55,47.1 r2.5
  lines w0.2: 16,0.1 16,49.8
  text "1" at 4.5,28.4 h2
  text "2" at 10.2,28.4 h2
  text "19" at 4.1,20.7 h2
  text "20" at 11.1,20.5 h2
  text "Solder Mask Spared for Cooling" at 65,9.5 h3
Shielding:
  circle w0.3: c44,36 r1.2
  circle w0.3: c44,4 r1.2
  circle w0.3: c77,20 r1.2
  lines w0.2: 65.2,7.2 65.2,10.8 68.8,10.8 68.8,7.2 65.2,7.2 ; 65.2,13.2 65.2,16.8 68.8,16.8 68.8,13.2 65.2,13.2 ; 65.2,23.2 68.8,23.2 68.8,26.8 65.2,26.8 65.2,23.2 ; 65.2,29.2 68.8,29.2 68.8,32.8 65.2,32.8 65.2,29.2 ; 70.2,7.2 73.8,7.2 73.8,10.8 70.2,10.8 70.2,7.2 ; 70.2,13.2 70.2,16.8 73.8,16.8 73.8,13.2 70.2,13.2 ; 70.2,23.2 70.2,26.8 73.8,26.8 73.8,23.2 70.2,23.2 ; 70.2,29.2 70.2,32.8 73.8,32.8 73.8,29.2 70.2,29.2
  lines w0.3: 38.875,2.425 38.875,4.425 ; 38.875,5.95 38.875,7.95 ; 38.875,9.475 38.875,11.475 ; 38.875,13 38.875,15 ; 38.875,16.525 38.875,18.525 ; 38.875,20.05 38.875,22.05 ; 38.875,23.575 38.875,25.575 ; 38.875,27.1 38.875,29.1 ; 38.875,30.625 38.875,32.625 ; 38.875,34.15 38.875,36.15 ; 38.875,37.675 38.875,37.9 ; 40.4,0.9 42.4,0.9 ; 40.4,39.1 42.4,39.1 ; 43.925,0.9 45.925,0.9 ; 43.925,39.1 45.925,39.1 ; 47.45,0.9 49.45,0.9 ; 47.45,39.1 49.45,39.1 ; 50.975,0.9 52.975,0.9 ; 50.975,39.1 52.975,39.1 ; 54.5,0.9 56.5,0.9 ; 54.5,39.1 56.5,39.1 ; 58.025,0.9 60.025,0.9 ; 58.025,39.1 60.025,39.1 ; 61.55,0.9 63.55,0.9 ; 61.55,39.1 63.55,39.1 ; 65.075,0.9 67.075,0.9 ; 65.075,39.1 67.075,39.1 ; 68.6,0.9 70.6,0.9 ; 68.6,39.1 70.6,39.1 ; 72.125,0.9 74.125,0.9 ; 72.125,39.1 74.125,39.1 ; 75.65,0.9 77.65,0.9 ; 75.65,39.1 77.65,39.1 ; 79.2,2.425 79.2,4.425 ; 79.2,5.95 79.2,7.95 ; 79.2,9.475 79.2,11.475 ; 79.2,13 79.2,15 ; 79.2,16.525 79.2,18.525 ; 79.2,20.05 79.2,22.05 ; 79.2,23.575 79.2,25.575 ; 79.2,27.1 79.2,29.1 ; 79.2,30.625 79.2,32.625 ; 79.2,34.15 79.2,36.15 ; 79.2,37.675 79.2,37.9 ; 36.875,0.9 36.875,39.1 38.875,39.1 38.875,41.1 79.2,41.1 79.2,39.1 81.2,39.1 81.2,0.9 79.2,0.9 79.2,-1.1 38.875,-1.1 38.875,0.9 36.875,0.9
  text "Blechdicke: 0.2mm" at 16.4,-3.6 h3
  text "Schirmhöhe: 2mm" at 16.4,-6.2 h3
Mechanical 15:
  lines w0.3: -3.476,97.241 34,71 ; 4.5,56 4.5,68 ; 4.5,60 6.5,60 6.5,64 8.5,64 ; 8.5,56 8.5,68 ; 32.25,69.75 32.25,71 35.75,71 35.75,69.75 ; 34,72 34,71 ; 34,73 34,75.5 ; 34,76.5 34,77.5 ; 34,78.5 34,81 ; 34,82 34,83 ; 53,68 53,70 ; 55,56 55,61 75,61 75,56 ; 59.098,61 59.098,67 65,67 70.902,67 70.902,61 ; 60,67 60,79.5 ; 60,68 0,68 0,70 60,70 ; 65,24.5 65,27 ; 65,28 65,29 ; 65,30 65,32.5 ; 65,33.5 65,34.5 ; 65,35.5 65,38 ; 65,39 65,40 ; 65,41 65,43.5 ; 65,44.5 65,45.5 ; 65,46.5 65,49 ; 65,50 65,51 ; 65,52 65,54.5 ; 65,55.5 65,56.5 ; 65,57.5 65,60 ; 65,61 65,62 ; 65,63 65,65.5 ; 65,66.5 65,67.5 ; 65,68.5 65,71 ; 65,79.5 65,82 65,84.5 ; 65,80 65,81 ; 65,83 65,84 ; 65,85.5 65,86.5 ; 70,67 70,79.5 ; 70,68 80,68 80,70 70,70 ; 71.476,97.241 34,71 ; 0,54 0,56 80,56 80,54 0,54 ; 54,79.5 54,87 76,87 76,79.5 54,79.5
  text "IlluminationBoard" at 11,70.5 h2
  text "SensorBoard" at 13.5,56.5 h2

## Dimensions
0,50 to 34,31.75 on TopDimHUM
52,25 to 65,38 on TopDimHUM
80,12 to 80,38 on TopDimHUM
79.2,41.1 to 73.8,32.8 on Shielding
73.8,32.8 to 81.2,39.1 on Shielding
73.8,29.2 to 73.8,32.8 on Shielding
73.8,26.8 to 81.2,39.1 on Shielding
73.8,23.2 to 73.8,26.8 on Shielding
73.8,16.8 to 73.8,23.2 on Shielding
73.8,13.2 to 73.8,16.8 on Shielding
81.2,0.9 to 73.8,13.2 on Shielding
73.8,10.8 to 73.8,7.2 on Shielding
65.2,32.8 to 68.8,32.8 on Shielding
73.8,7.2 to 81.2,0.9 on Shielding
79.2,41.1 to 68.8,32.8 on Shielding
70.2,32.8 to 73.8,32.8 on Shielding
44,37.2 to 38.875,41.1 on Shielding
38.875,-1.1 to 44,2.8 on Shielding
79.2,-1.1 to 77,18.8 on Shielding
78.2,20 to 81.2,39.1 on Shielding
81.2,0.9 to 78.2,20 on Shielding
42.8,36 to 36.875,39.1 on Shielding
42.8,4 to 42.8,36 on Shielding
36.875,0.9 to 42.8,4 on Shielding
44,4 to 45.6,5.8 on Shielding
79.2,-1.1 to 38.875,-1.1 on Shielding
36.875,0.9 to 36.875,39.1 on Shielding
79.3,13.2 to 27.6,0 on BotDimHUM
39.55,47.1 to 36.5,43.1 on BotDimHUM
39.55,47.1 to 42,43.7 on BotDimHUM
0,0 to 0,50 on BotDimHUM
0,50 to 79.3,36.8 on BotDimHUM
0,0 to 6,25 on BotDimHUM
0,50 to 7,26 on BotDimHUM
80,0 to 80,50 on BotDimProd
0,0 to 29.6,47.9 on BotDimProd
0,0 to 25,2.9 on BotDimProd
0,0 to 6.7,11.8 on BotDimProd
0,50 to 80,50 on BotDimProd
0,0 to 7.2,11.3 on BotDimProd
0,0 to 30.1,47.4 on BotDimProd
0,0 to 25.5,2.4 on BotDimProd
0,50 to 35,2.6 on TopDimProd
0,50 to 7.65,43.25 on TopDimProd
0,50 to 44.1,47.8 on TopDimProd
80,0 to 80,50 on TopDimProd
80,0 to 0,0 on TopDimProd
0,0 to 34.5,2.1 on TopDimProd
0,0 to 43.6,47.3 on TopDimProd
0,0 to 7.15,42.75 on TopDimProd
77.25,47.3 to 80,50 on TopDimHUM
80,0 to 80,12 on TopDimHUM
0,0 to 2.75,2.7 on TopDimHUM
77.25,2.7 to 80,0 on TopDimHUM
80,0 to 77.25,2.7 on TopDimHUM
39.55,47.1 to 80,50 on TopDimHUM
0,0 to 39.55,2.9 on TopDimHUM
2.75,2.7 to 2.75,47.3 on TopDimHUM
2.75,47.3 to 0,50 on TopDimHUM
0,50 to 39.55,47.1 on TopDimHUM
65,38 to 80,50 on TopDimHUM
2.75,47.3 to 5.3,45.1 on TopDimHUM
0,0 to 80,0 on TopDimHUM
0,50 to 0,0 on TopDimHUM
0,0 to 2.75,2.7 on TopDimHUM
0,0 to 39.55,2.9 on TopDimHUM
34,71 to 71.476,97.241 on Mechanical 15
34,83 to 65,84 on Mechanical 15
54,87 to 76,87 on Mechanical 15
76,87 to 80,56 on Mechanical 15
80,56 to 80,68 on Mechanical 15
0,70 to 34,83 on Mechanical 15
